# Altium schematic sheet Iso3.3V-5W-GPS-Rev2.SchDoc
size Tabloid; Organization: Monterey Bay Aquarium Research Institute; Address1: 7700 Sandholdt Rd; Address2: Moss Landing, CA 95039-9644; CompanyName: MBARI
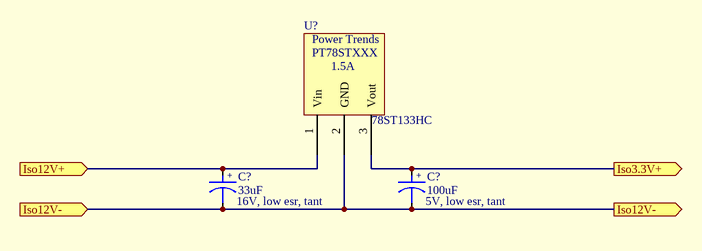
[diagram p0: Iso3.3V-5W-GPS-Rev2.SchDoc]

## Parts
(Parts that share a designator on the sheet are numbered #1, #2 ... from top to bottom, then left to right.)
C?#1  33uF  DescSheet: 16V, low esr, tant  [6032pol]
C?#2  100uF  DescSheet: 5V, low esr, tant  [6032pol]
U?  78ST133HC  [PT78ST-HORIZ]

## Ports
Iso3.3V+, Iso12V+, Iso12V-

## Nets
Iso3.3V+: C?#2.1 U?.3(Vout) ; port Iso3.3V+
Iso12V+: C?#1.1 U?.1(Vin) ; port Iso12V+
Iso12V-: C?#1.2 C?#2.2 U?.2(GND) ; port Iso12V-

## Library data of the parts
C?#1 = CAPACITOR POL: Capacitor; ManufPartNo: EEJ-L1CC336R; VendorPartNo: P11290CT-ND
C?#2 = CAPACITOR POL: Capacitor
U? = PT78STXXX: Power Trends Switching Reg; Manufacturer: TI Power Trends; VendorPartNo: 78ST133HC-ND; Cost/ea: 15.38; Reference: T033, 1102; Vendor: Digi-Key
